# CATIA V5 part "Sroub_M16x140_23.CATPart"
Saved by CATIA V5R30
Part number: Sroub_M16x140_23
Definition: E 1200_16x140
Nomenclature: E 1200_16x140
Source: Unknown
Description: PART--DESC
Bounding box of the stored display mesh (mm): x 128 to 152, y -148.99 to -125.01, z -24.3 to 131.7
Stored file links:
  E:\Bakalarka\Model\Forma_v7\Sroub_M16x140_23.CATPart
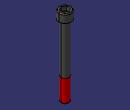
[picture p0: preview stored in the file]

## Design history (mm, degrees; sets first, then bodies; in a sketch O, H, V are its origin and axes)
Body1 "MANIFOLD_SOLID_BREP #3842" (main body)
  Solid1: solid without history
